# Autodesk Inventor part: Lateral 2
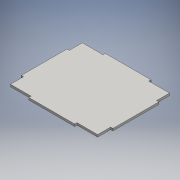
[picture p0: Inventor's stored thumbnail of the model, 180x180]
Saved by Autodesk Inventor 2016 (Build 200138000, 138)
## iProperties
Created: 2016-06
Part Number: Lateral 2
Material: Genérico
Document SubType Name: Modeling
Designer: adm
Density: 1 g/cm^3
Appearance: Valor por defecto
Author: adm
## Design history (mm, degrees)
sketch "Boceto1"
  geometry: L1 (-1.771, 50)-(30, 50); L2 (60, 30)-(60, -30); L3 (30, -50)-(0, -50); L4 (57, -47)-(57, -30); L5 (57, 30)-(57, 47); L6 (57, 47)-(30, 47); L7 (30, -47)-(57, -47); L8 (30, -47)-(30, -50); L9 (30, 50)-(30, 47); L10 (57, -30)-(60, -30); L11 (57, 30)-(60, 30); L12 (-1.771, 50)-(-30, 50); L13 (-60, 30)-(-60, -30); L14 (-30, -50)-(0, -50); L15 (-57, -47)-(-57, -30); L16 (-57, 30)-(-57, 47); L17 (-57, 47)-(-30, 47); L18 (-30, -47)-(-57, -47); L19 (-30, -47)-(-30, -50); L20 (-30, 50)-(-30, 47); L21 (-57, -30)-(-60, -30); L22 (-57, 30)-(-60, 30); 1 further point
  constraints: 44 end point, 3 perpendicular, 2 parallel, 1 horizontal
  dimensions: "d0" = 94 distance of L4.start L5.end; "d1" = 3 distance between parallel lines of L6 L1; "d8" = 60 distance between parallel lines of L21 L22; "d9" = 17 distance between parallel lines of L22 L17; "d10" = 17 distance between parallel lines of L21 L18; "d11" = 60 distance of L2.start L2.end; "d13" = 17 distance between parallel lines of L11 L6; "d14" = 3 distance between parallel lines of L16 L13; "d15" = 3 distance between parallel lines of L5 L2; "d16" = 120 distance between parallel lines of L13 L2; "d17" = 60 distance between parallel lines of L20 L9; "d18" = 27 distance between parallel lines of L9 L5; "d19" = 60 distance between parallel lines of L8 L19; "d21" = 27 distance between parallel lines of L8 L4; "d22" = 27 distance between parallel lines of L19 L15; "d23" = 3 distance between parallel lines of L15 L13; "d24" = 17 distance between parallel lines of L7 L10 (derived)
extrude "Extrusión1" new body sketch "Boceto1" distance "d2" = 3; taper "d3" = 0 deg
node "Sólido1"
